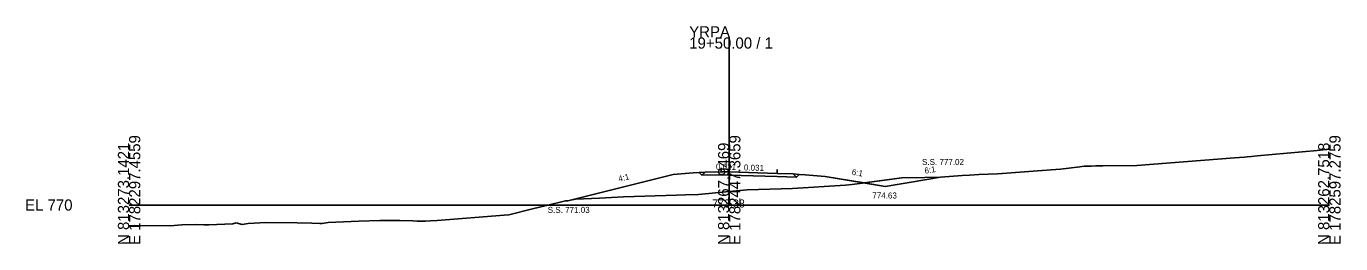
# Model space of a CAD drawing. Extents: x -26 to 2603, y -14 to 9545.
# Drawn here: x -25.7 to 302.8, y 9490.3 to 9544.7 of the extents above; entities that cross this region are included whole.
import ezdxf

# ---------------------------------------------------------------- set-up
doc = ezdxf.new("R2010")
doc.units = 0
for name, color, linetype in [('Exist Cross Section Cell', 7, 'Continuous'), ('Exist XS Center Line Elevation Label', 7, 'Continuous'), ('Exist XS Ground Line', 7, 'Continuous'), ('Prop XS Ditch Slope Text', 7, 'Continuous'), ('Prop XS Ditch Standard Text', 7, 'Continuous'), ('Prop XS Dump Level', 7, 'Continuous'), ('Prop XS Earthwork Shape', 7, 'Continuous'), ('Prop XS EOT Tick Mark', 7, 'Continuous'), ('Prop XS Finish Grade', 7, 'Continuous'), ('Prop XS Finish Grade Earthwork', 7, 'Continuous'), ('Prop XS Finish Grade Paved Shoulder', 7, 'Continuous'), ('Prop XS Finish Grade Pavement', 7, 'Continuous'), ('Prop XS Hydro Fill Slope Data', 7, 'Continuous'), ('Prop XS Pvmt Edge Slope', 7, 'Continuous'), ('Prop XS SE Text', 7, 'Continuous'), ('Prop XS Side Slope Text', 7, 'Continuous'), ('Prop XS SS Elevation Text', 7, 'Continuous'), ('Prop XS Subgrade Earthwork', 7, 'Continuous')]:
    doc.layers.add(name, color=color, linetype=linetype)

msp = doc.modelspace()

# ---------------------------------------------------------------- linework, layer by layer
at = {"layer": 'Exist Cross Section Cell'}
for p, q in [((150, 9500), (150, 9541.93)), ((0, 9500), (150, 9500)), ((150, 9500), (300, 9500))]:
    msp.add_line(p, q, dxfattribs=at)
at = {"layer": 'Exist XS Ground Line'}
for p, q in [((251.9, 9509.88), (276.28, 9511.84)), ((276.28, 9511.84), (278.81, 9512)), ((278.81, 9512), (279.49, 9512.04)), ((279.49, 9512.04), (280.54, 9512.12)), ((280.54, 9512.12), (281.97, 9512.28)), ((281.97, 9512.28), (296.98, 9513.64)), ((296.98, 9513.64), (300, 9513.98)), ((212.43, 9507.62), (217.02, 9507.81)), ((217.02, 9507.81), (219.35, 9507.97)), ((219.35, 9507.97), (227.05, 9508.53)), ((227.05, 9508.53), (231.62, 9508.85)), ((231.62, 9508.85), (232.79, 9508.96)), ((232.79, 9508.96), (237.66, 9509.55)), ((237.66, 9509.55), (238.74, 9509.68)), ((238.74, 9509.68), (240.49, 9509.71)), ((240.49, 9509.71), (241.65, 9509.78)), ((241.65, 9509.78), (243.37, 9509.8)), ((243.37, 9509.8), (251.9, 9509.88)), ((165.78, 9504.14), (179.04, 9504.99)), ((179.04, 9504.99), (180.65, 9505.12)), ((180.65, 9505.12), (183.28, 9505.45)), ((183.28, 9505.45), (193.16, 9506.84)), ((193.16, 9506.84), (198.92, 9506.9)), ((198.92, 9506.9), (202.78, 9506.98)), ((202.78, 9506.98), (208.21, 9507.38)), ((208.21, 9507.38), (210.03, 9507.5)), ((210.03, 9507.5), (212.43, 9507.62)), ((109.68, 9501.03), (111.12, 9501.34)), ((111.12, 9501.34), (111.62, 9501.45)), ((111.62, 9501.45), (117.56, 9501.74)), ((117.56, 9501.74), (123.59, 9502.01)), ((123.59, 9502.01), (136.79, 9502.48)), ((136.79, 9502.48), (139.06, 9502.58)), ((139.06, 9502.58), (142.33, 9502.66)), ((142.33, 9502.66), (150, 9503.38)), ((150, 9503.38), (154.5, 9503.8)), ((154.5, 9503.8), (165.78, 9504.14)), ((94.92, 9497.58), (100.84, 9499)), ((100.84, 9499), (104.36, 9499.84)), ((104.36, 9499.84), (109.09, 9501.03)), ((109.09, 9501.03), (109.68, 9501.03)), ((0, 9494.78), (1.23, 9494.84)), ((1.23, 9494.84), (10.25, 9494.8)), ((10.25, 9494.8), (13.19, 9495.05)), ((13.19, 9495.05), (16.7, 9495.08)), ((16.7, 9495.08), (18.71, 9495.05)), ((18.71, 9495.05), (19.91, 9495.03)), ((19.91, 9495.03), (25.93, 9495.32)), ((25.93, 9495.32), (26.79, 9495.54)), ((26.79, 9495.54), (28.3, 9495.12)), ((28.3, 9495.12), (29.79, 9495.37)), ((29.79, 9495.37), (34.16, 9495.59)), ((34.16, 9495.59), (42.02, 9495.55)), ((42.02, 9495.55), (45.65, 9495.42)), ((45.65, 9495.42), (47.68, 9495.36)), ((47.68, 9495.36), (48.29, 9495.39)), ((48.29, 9495.39), (49.73, 9495.66)), ((49.73, 9495.66), (57.46, 9495.94)), ((57.46, 9495.94), (62.64, 9496.11)), ((62.64, 9496.11), (67.69, 9496.1)), ((67.69, 9496.1), (70.92, 9496.01)), ((70.92, 9496.01), (72.03, 9495.97)), ((72.03, 9495.97), (74.12, 9495.98)), ((74.12, 9495.98), (75.33, 9496.01)), ((75.33, 9496.01), (77.03, 9496.11)), ((77.03, 9496.11), (93.71, 9497.46)), ((93.71, 9497.46), (94.92, 9497.58))]:
    msp.add_line(p, q, dxfattribs=at)
at = {"layer": 'Prop XS Dump Level'}
for p, q in [((148, 9508.33), (150, 9508.27)), ((150, 9508.27), (162, 9507.9))]:
    msp.add_line(p, q, dxfattribs=at)
at = {"layer": 'Prop XS Earthwork Shape'}
for points in [[(161.98, 9507.11), (166.82, 9506.95), (167.51, 9507.65), (169, 9507.53), (174, 9507.13), (183.71, 9505.51), (183.28, 9505.45), (180.65, 9505.12), (179.04, 9504.99), (165.78, 9504.14), (154.5, 9503.8), (150, 9503.38), (142.33, 9502.66), (139.06, 9502.58), (136.79, 9502.48), (123.59, 9502.01), (117.56, 9501.74), (111.62, 9501.45), (111.12, 9501.34), (109.68, 9501.03), (109.66, 9501.03), (136, 9507.61), (141, 9508.01), (142.5, 9508.13), (143.19, 9507.45), (148, 9507.54), (149.98, 9507.48)], [(183.71, 9505.51), (193.16, 9506.84), (198.92, 9506.9), (202.78, 9506.98), (203.35, 9507.02), (195, 9505.63), (189, 9504.63)]]:
    msp.add_lwpolyline(points, close=True, dxfattribs=at)
at = {"layer": 'Prop XS EOT Tick Mark'}
for p, q in [((148, 9508.33), (148, 9509.33)), ((162, 9507.9), (162, 9508.9))]:
    msp.add_line(p, q, dxfattribs=at)
at = {"layer": 'Prop XS Finish Grade'}
for p, q in [((144, 9508.25), (142.5, 9508.13)), ((166, 9507.77), (167.51, 9507.65))]:
    msp.add_line(p, q, dxfattribs=at)
at = {"layer": 'Prop XS Finish Grade Earthwork'}
for p, q in [((136, 9507.61), (141, 9508.01)), ((141, 9508.01), (142.5, 9508.13)), ((136, 9507.61), (109.66, 9501.03)), ((167.51, 9507.65), (169, 9507.53)), ((169, 9507.53), (174, 9507.13)), ((174, 9507.13), (189, 9504.63)), ((189, 9504.63), (195, 9505.63)), ((195, 9505.63), (203.35, 9507.02))]:
    msp.add_line(p, q, dxfattribs=at)
at = {"layer": 'Prop XS Finish Grade Paved Shoulder'}
for p, q in [((148, 9508.33), (144, 9508.25)), ((162, 9507.9), (166, 9507.77))]:
    msp.add_line(p, q, dxfattribs=at)
at = {"layer": 'Prop XS Finish Grade Pavement'}
for p, q in [((148, 9508.33), (150, 9508.27)), ((150, 9508.27), (162, 9507.9))]:
    msp.add_line(p, q, dxfattribs=at)
at = {"layer": 'Prop XS Hydro Fill Slope Data'}
msp.add_line((136, 9507.61), (109.66, 9501.03), dxfattribs=at)
at = {"layer": 'Prop XS Pvmt Edge Slope'}
for p, q in [((144, 9508.25), (143.19, 9507.45)), ((166, 9507.77), (166.82, 9506.95))]:
    msp.add_line(p, q, dxfattribs=at)
at = {"layer": 'Prop XS Subgrade Earthwork'}
for p, q in [((143.19, 9507.45), (142.5, 9508.13)), ((148, 9507.54), (143.19, 9507.45)), ((148, 9507.54), (149.98, 9507.48)), ((149.98, 9507.48), (161.98, 9507.11)), ((161.98, 9507.11), (166.82, 9506.95)), ((166.82, 9506.95), (167.51, 9507.65))]:
    msp.add_line(p, q, dxfattribs=at)

# ---------------------------------------------------------------- texts
at = {"layer": 'Exist Cross Section Cell'}
for s, p in [('YRPA', (140, 9541.93)), ('19+50.00 / 1', (140, 9539.13)), ('EL 770', (-26, 9498.6))]:
    msp.add_text(s, height=2.8, dxfattribs=at).set_placement(p)
for s, p in [('N 813273.1421', (0, 9490)), ('E 1782297.4559', (2.8, 9490)), ('N 813267.9469', (150, 9490)), ('E 1782447.3659', (152.8, 9490)), ('N 813262.7518', (300, 9490)), ('E 1782597.2759', (302.8, 9490))]:
    msp.add_text(s, height=2.8, rotation=90, dxfattribs=at).set_placement(p)
at = {"layer": 'Exist XS Center Line Elevation Label'}
msp.add_text('773.38', height=2, dxfattribs=at).set_placement((145.73, 9499.38))
at = {"layer": 'Prop XS Ditch Slope Text'}
msp.add_text('6:1', height=1.5, rotation=350.5377, dxfattribs=at).set_placement((180.55, 9507.56))
at = {"layer": 'Prop XS Ditch Standard Text'}
msp.add_text('774.63', height=1.5, dxfattribs=at).set_placement((185.77, 9501.63))
at = {"layer": 'Prop XS Dump Level'}
for p in [(136, 9507.57), (174, 9507.09)]:
    msp.add_text('Case4', height=0.04, dxfattribs=at).set_placement(p)
at = {"layer": 'Prop XS SE Text'}
for p in [(146.65, 9508.88), (153.65, 9508.66)]:
    msp.add_text('0.031', height=1.5, rotation=358.2143, dxfattribs=at).set_placement(p)
at = {"layer": 'Prop XS Side Slope Text'}
for s, rotation, p in [('4:1', 14.0362, (122.46, 9505.78)), ('6:1', 9.4623, (198.93, 9507.81))]:
    msp.add_text(s, height=1.5, rotation=rotation, dxfattribs=at).set_placement(p)
at = {"layer": 'Prop XS SS Elevation Text'}
for s, p in [('S.S. 777.02', (198.2, 9510.02)), ('S.S. 771.03', (104.64, 9498.03))]:
    msp.add_text(s, height=1.5, dxfattribs=at).set_placement(p)

doc.saveas('drawing.dxf')
